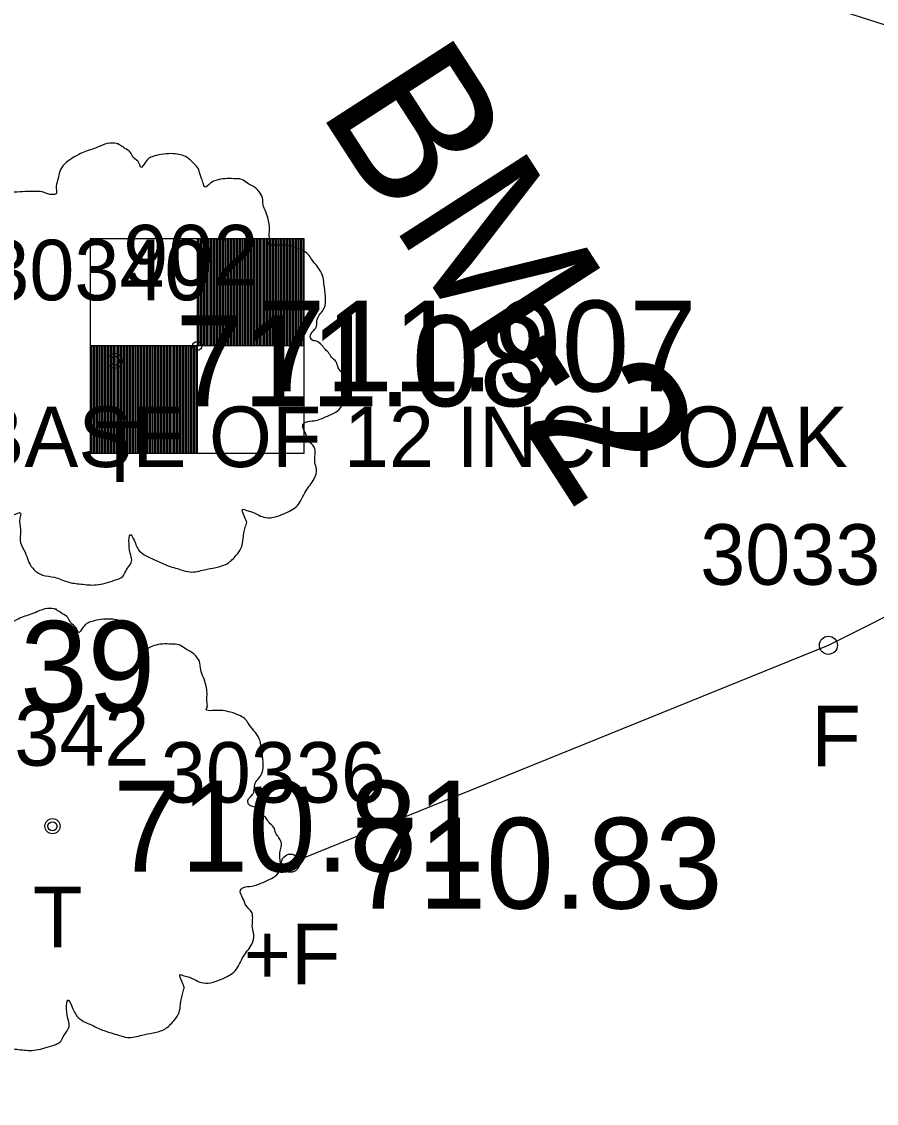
# Model space of a CAD drawing. Extents: x 1375131 to 1378678, y 999028 to 1004053.
# Drawn here: x 1377561.15 to 1377575.26, y 1001420.88 to 1001438.75 of the extents above; entities that cross this region are included whole.
import ezdxf

# ---------------------------------------------------------------- set-up
doc = ezdxf.new("R2010")
doc.units = 0
for name, color, linetype in [('RD_EX_Fence_Other', 7, 'Continuous'), ('RD_EX_Fence_Other_txCode', 7, 'Continuous'), ('RD_EX_SU_Elec', 7, 'Continuous'), ('RD_EX_TX_Fence_Other_ELEV', 7, 'Continuous'), ('RD_EX_TX_VEG_ELEV', 7, 'Continuous'), ('RD_EX_VEG', 7, 'Continuous'), ('RD_EX_VEG_txCode', 7, 'Continuous'), ('RD_HC_Survey', 7, 'Continuous'), ('RD_HC_Survey_ELEV', 7, 'Continuous'), ('RD_HC_Survey_txCode', 7, 'Continuous'), ('RD_SMD_Locator', 7, 'Continuous'), ('RD_TX_Misc1', 7, 'Continuous')]:
    doc.layers.add(name, color=color, linetype=linetype)

msp = doc.modelspace()

# ---------------------------------------------------------------- linework, layer by layer
at = {"layer": 'RD_EX_Fence_Other'}
msp.add_lwpolyline([(1377565.589, 1001424.844), (1377574.472, 1001428.444), (1377584.337, 1001433.395), (1377590.636, 1001436.43)], dxfattribs=at)
at = {"layer": 'RD_EX_SU_Elec'}
msp.add_line((1377525.757, 1001454.692), (1377701.052, 1001398.203), dxfattribs=at)
at = {"layer": 'RD_EX_VEG'}
for centre, radius in [((1377562.69, 1001433.143), 0.125), ((1377562.684, 1001433.134), 0.00005), ((1377561.659, 1001425.455), 0.125), ((1377561.653, 1001425.446), 0.00005)]:
    msp.add_circle(centre, radius, dxfattribs=at)
for points in [[(1377562.756, 1001436.727), (1377562.606, 1001436.739), (1377562.444, 1001436.689), (1377562.319, 1001436.639), (1377562.206, 1001436.602), (1377562.094, 1001436.552), (1377561.944, 1001436.464), (1377561.831, 1001436.364), (1377561.769, 1001436.239), (1377561.744, 1001436.127), (1377561.719, 1001435.989), (1377561.719, 1001435.902), (1377561.656, 1001435.889), (1377561.581, 1001435.902), (1377561.457, 1001435.939), (1377561.332, 1001435.939), (1377561.207, 1001435.939), (1377561.032, 1001435.927), (1377560.857, 1001435.927), (1377560.719, 1001435.902), (1377560.557, 1001435.877), (1377560.37, 1001435.815), (1377560.195, 1001435.752), (1377560.045, 1001435.627), (1377559.92, 1001435.39), (1377559.857, 1001435.215), (1377559.782, 1001435.09), (1377559.857, 1001434.865), (1377559.945, 1001434.69), (1377559.957, 1001434.59), (1377559.995, 1001434.378), (1377560.045, 1001434.265), (1377560.107, 1001434.165), (1377560.07, 1001434.153), (1377559.882, 1001434.128), (1377559.732, 1001434.078), (1377559.52, 1001433.965), (1377559.407, 1001433.853), (1377559.357, 1001433.69), (1377559.345, 1001433.516), (1377559.295, 1001433.416), (1377559.258, 1001433.278), (1377559.245, 1001433.241), (1377559.22, 1001433.078), (1377559.27, 1001432.853), (1377559.283, 1001432.678), (1377559.345, 1001432.566), (1377559.42, 1001432.479), (1377559.507, 1001432.354), (1377559.707, 1001432.241), (1377559.87, 1001432.191), (1377559.97, 1001432.179), (1377559.882, 1001431.929), (1377559.857, 1001431.754), (1377559.795, 1001431.554), (1377559.795, 1001431.516), (1377559.77, 1001431.279), (1377559.845, 1001431.117), (1377559.882, 1001430.929), (1377559.97, 1001430.817), (1377560.107, 1001430.667), (1377560.27, 1001430.554), (1377560.519, 1001430.492), (1377560.719, 1001430.504), (1377561.007, 1001430.592), (1377561.132, 1001430.629), (1377561.119, 1001430.542), (1377561.132, 1001430.354), (1377561.132, 1001430.142), (1377561.207, 1001429.98), (1377561.257, 1001429.842), (1377561.332, 1001429.717), (1377561.494, 1001429.605), (1377561.694, 1001429.567), (1377561.906, 1001429.492), (1377562.131, 1001429.455), (1377562.381, 1001429.442), (1377562.681, 1001429.517), (1377562.818, 1001429.58), (1377562.868, 1001429.667), (1377562.968, 1001429.855), (1377562.943, 1001429.967), (1377562.956, 1001430.267), (1377563.006, 1001430.179), (1377563.093, 1001430.005), (1377563.343, 1001429.855), (1377563.543, 1001429.767), (1377563.781, 1001429.692), (1377563.93, 1001429.655), (1377564.168, 1001429.692), (1377564.355, 1001429.73), (1377564.543, 1001429.792), (1377564.693, 1001429.93), (1377564.78, 1001430.067), (1377564.805, 1001430.204), (1377564.843, 1001430.392), (1377564.868, 1001430.479)], [(1377564.868, 1001430.479), (1377564.83, 1001430.567), (1377564.805, 1001430.692), (1377564.843, 1001430.679), (1377564.93, 1001430.654), (1377565.067, 1001430.592), (1377565.18, 1001430.554), (1377565.342, 1001430.567), (1377565.48, 1001430.617), (1377565.705, 1001430.754), (1377565.842, 1001430.992), (1377565.98, 1001431.192), (1377566.017, 1001431.354), (1377565.992, 1001431.466), (1377565.98, 1001431.716), (1377565.88, 1001431.841), (1377565.855, 1001431.904), (1377565.805, 1001432.104), (1377565.842, 1001432.129), (1377565.98, 1001432.154), (1377566.167, 1001432.216), (1377566.304, 1001432.279), (1377566.417, 1001432.366), (1377566.454, 1001432.479), (1377566.442, 1001432.678), (1377566.467, 1001432.878), (1377566.429, 1001432.953), (1377566.379, 1001433.028), (1377566.342, 1001433.128), (1377566.267, 1001433.203), (1377566.217, 1001433.278), (1377566.167, 1001433.328), (1377566.105, 1001433.403), (1377566.017, 1001433.466), (1377565.942, 1001433.491), (1377565.917, 1001433.566), (1377565.992, 1001433.665), (1377566.017, 1001433.715), (1377566.03, 1001433.828), (1377566.142, 1001434.003), (1377566.167, 1001434.203), (1377566.142, 1001434.415), (1377566.117, 1001434.553), (1377566.042, 1001434.69), (1377565.942, 1001434.815), (1377565.88, 1001434.902), (1377565.792, 1001434.965), (1377565.63, 1001435.027), (1377565.505, 1001435.052), (1377565.33, 1001435.052), (1377565.23, 1001435.077), (1377565.242, 1001435.102), (1377565.242, 1001435.177), (1377565.242, 1001435.315), (1377565.205, 1001435.54), (1377565.13, 1001435.79), (1377565.13, 1001435.802), (1377565.08, 1001435.927), (1377564.968, 1001436.027), (1377564.88, 1001436.077), (1377564.78, 1001436.139), (1377564.655, 1001436.152), (1377564.505, 1001436.152), (1377564.368, 1001436.127), (1377564.268, 1001436.077), (1377564.18, 1001436.014), (1377564.143, 1001436.089), (1377564.093, 1001436.239), (1377564.068, 1001436.314), (1377563.993, 1001436.402), (1377563.881, 1001436.502), (1377563.656, 1001436.564), (1377563.343, 1001436.527), (1377563.193, 1001436.427), (1377563.118, 1001436.339), (1377563.093, 1001436.402), (1377562.993, 1001436.502), (1377562.943, 1001436.589), (1377562.856, 1001436.652), (1377562.781, 1001436.702), (1377562.731, 1001436.727)], [(1377561.725, 1001429.039), (1377561.575, 1001429.051), (1377561.413, 1001429.001), (1377561.288, 1001428.951), (1377561.175, 1001428.914), (1377561.063, 1001428.864), (1377560.913, 1001428.776), (1377560.8, 1001428.676), (1377560.738, 1001428.551), (1377560.713, 1001428.439), (1377560.688, 1001428.301), (1377560.688, 1001428.214), (1377560.625, 1001428.201), (1377560.55, 1001428.214), (1377560.426, 1001428.251), (1377560.301, 1001428.251), (1377560.176, 1001428.251), (1377560.001, 1001428.239), (1377559.826, 1001428.239), (1377559.688, 1001428.214), (1377559.526, 1001428.189), (1377559.339, 1001428.127), (1377559.164, 1001428.064), (1377559.014, 1001427.939), (1377558.889, 1001427.702), (1377558.826, 1001427.527), (1377558.751, 1001427.402), (1377558.826, 1001427.177), (1377558.914, 1001427.002), (1377558.926, 1001426.902), (1377558.964, 1001426.69), (1377559.014, 1001426.577), (1377559.076, 1001426.477), (1377559.039, 1001426.465), (1377558.851, 1001426.44), (1377558.701, 1001426.39), (1377558.489, 1001426.277), (1377558.376, 1001426.165), (1377558.326, 1001426.002), (1377558.314, 1001425.828), (1377558.264, 1001425.728), (1377558.227, 1001425.59), (1377558.214, 1001425.553), (1377558.189, 1001425.39), (1377558.239, 1001425.165), (1377558.252, 1001424.99), (1377558.314, 1001424.878), (1377558.389, 1001424.791), (1377558.476, 1001424.666), (1377558.676, 1001424.553), (1377558.839, 1001424.503), (1377558.939, 1001424.491), (1377558.851, 1001424.241), (1377558.826, 1001424.066), (1377558.764, 1001423.866), (1377558.764, 1001423.828), (1377558.739, 1001423.591), (1377558.814, 1001423.429), (1377558.851, 1001423.241), (1377558.939, 1001423.129), (1377559.076, 1001422.979), (1377559.239, 1001422.866), (1377559.488, 1001422.804), (1377559.688, 1001422.816), (1377559.976, 1001422.904), (1377560.101, 1001422.941), (1377560.088, 1001422.854), (1377560.101, 1001422.666), (1377560.101, 1001422.454), (1377560.176, 1001422.292), (1377560.226, 1001422.154), (1377560.301, 1001422.029), (1377560.463, 1001421.917), (1377560.663, 1001421.879), (1377560.875, 1001421.804), (1377561.1, 1001421.767), (1377561.35, 1001421.754), (1377561.65, 1001421.829), (1377561.787, 1001421.892), (1377561.837, 1001421.979), (1377561.937, 1001422.167), (1377561.912, 1001422.279), (1377561.925, 1001422.579), (1377561.975, 1001422.491), (1377562.062, 1001422.317), (1377562.312, 1001422.167), (1377562.512, 1001422.079), (1377562.75, 1001422.004), (1377562.899, 1001421.967), (1377563.137, 1001422.004), (1377563.324, 1001422.042), (1377563.512, 1001422.104), (1377563.662, 1001422.242), (1377563.749, 1001422.379), (1377563.774, 1001422.516), (1377563.812, 1001422.704), (1377563.837, 1001422.791)], [(1377563.837, 1001422.791), (1377563.799, 1001422.879), (1377563.774, 1001423.004), (1377563.812, 1001422.991), (1377563.899, 1001422.966), (1377564.036, 1001422.904), (1377564.149, 1001422.866), (1377564.311, 1001422.879), (1377564.449, 1001422.929), (1377564.674, 1001423.066), (1377564.811, 1001423.304), (1377564.949, 1001423.504), (1377564.986, 1001423.666), (1377564.961, 1001423.778), (1377564.949, 1001424.028), (1377564.849, 1001424.153), (1377564.824, 1001424.216), (1377564.774, 1001424.416), (1377564.811, 1001424.441), (1377564.949, 1001424.466), (1377565.136, 1001424.528), (1377565.273, 1001424.591), (1377565.386, 1001424.678), (1377565.423, 1001424.791), (1377565.411, 1001424.99), (1377565.436, 1001425.19), (1377565.398, 1001425.265), (1377565.348, 1001425.34), (1377565.311, 1001425.44), (1377565.236, 1001425.515), (1377565.186, 1001425.59), (1377565.136, 1001425.64), (1377565.074, 1001425.715), (1377564.986, 1001425.778), (1377564.911, 1001425.803), (1377564.886, 1001425.878), (1377564.961, 1001425.977), (1377564.986, 1001426.027), (1377564.999, 1001426.14), (1377565.111, 1001426.315), (1377565.136, 1001426.515), (1377565.111, 1001426.727), (1377565.086, 1001426.865), (1377565.011, 1001427.002), (1377564.911, 1001427.127), (1377564.849, 1001427.214), (1377564.761, 1001427.277), (1377564.599, 1001427.339), (1377564.474, 1001427.364), (1377564.299, 1001427.364), (1377564.199, 1001427.389), (1377564.211, 1001427.414), (1377564.211, 1001427.489), (1377564.211, 1001427.627), (1377564.174, 1001427.852), (1377564.099, 1001428.102), (1377564.099, 1001428.114), (1377564.049, 1001428.239), (1377563.937, 1001428.339), (1377563.849, 1001428.389), (1377563.749, 1001428.451), (1377563.624, 1001428.464), (1377563.474, 1001428.464), (1377563.337, 1001428.439), (1377563.237, 1001428.389), (1377563.149, 1001428.326), (1377563.112, 1001428.401), (1377563.062, 1001428.551), (1377563.037, 1001428.626), (1377562.962, 1001428.714), (1377562.85, 1001428.814), (1377562.625, 1001428.876), (1377562.312, 1001428.839), (1377562.162, 1001428.739), (1377562.087, 1001428.651), (1377562.062, 1001428.714), (1377561.962, 1001428.814), (1377561.912, 1001428.901), (1377561.825, 1001428.964), (1377561.75, 1001429.014), (1377561.7, 1001429.039)]]:
    msp.add_spline(points, degree=3, dxfattribs=at)
at = {"layer": 'RD_HC_Survey'}
for p, q in [((1377564.048, 1001435.156), (1377564.048, 1001431.62)), ((1377564.066, 1001435.156), (1377564.066, 1001433.388)), ((1377564.091, 1001435.156), (1377564.091, 1001433.388)), ((1377564.116, 1001435.156), (1377564.116, 1001433.388)), ((1377564.141, 1001435.156), (1377564.141, 1001433.388)), ((1377564.166, 1001435.156), (1377564.166, 1001433.388)), ((1377564.191, 1001435.156), (1377564.191, 1001433.388)), ((1377564.216, 1001435.156), (1377564.216, 1001433.388)), ((1377564.241, 1001435.156), (1377564.241, 1001433.388)), ((1377564.266, 1001435.156), (1377564.266, 1001433.388)), ((1377564.291, 1001435.156), (1377564.291, 1001433.388)), ((1377564.316, 1001435.156), (1377564.316, 1001433.388)), ((1377564.341, 1001435.156), (1377564.341, 1001433.388)), ((1377564.366, 1001435.156), (1377564.366, 1001433.388)), ((1377564.391, 1001435.156), (1377564.391, 1001433.388)), ((1377564.416, 1001435.156), (1377564.416, 1001433.388)), ((1377564.441, 1001435.156), (1377564.441, 1001433.388)), ((1377564.466, 1001435.156), (1377564.466, 1001433.388)), ((1377564.491, 1001435.156), (1377564.491, 1001433.388)), ((1377564.516, 1001435.156), (1377564.516, 1001433.388)), ((1377564.541, 1001435.156), (1377564.541, 1001433.388)), ((1377564.566, 1001435.156), (1377564.566, 1001433.388)), ((1377564.591, 1001435.156), (1377564.591, 1001433.388)), ((1377564.616, 1001435.156), (1377564.616, 1001433.388)), ((1377564.641, 1001435.156), (1377564.641, 1001433.388)), ((1377564.666, 1001435.156), (1377564.666, 1001433.388)), ((1377564.691, 1001435.156), (1377564.691, 1001433.388)), ((1377564.716, 1001435.156), (1377564.716, 1001433.388)), ((1377564.741, 1001435.156), (1377564.741, 1001433.388)), ((1377564.766, 1001435.156), (1377564.766, 1001433.388)), ((1377564.791, 1001435.156), (1377564.791, 1001433.388)), ((1377564.816, 1001435.156), (1377564.816, 1001433.388)), ((1377564.841, 1001435.156), (1377564.841, 1001433.388)), ((1377564.866, 1001435.156), (1377564.866, 1001433.388)), ((1377564.891, 1001435.156), (1377564.891, 1001433.388)), ((1377564.916, 1001435.156), (1377564.916, 1001433.388)), ((1377564.941, 1001435.156), (1377564.941, 1001433.388)), ((1377564.966, 1001435.156), (1377564.966, 1001433.388)), ((1377564.991, 1001435.156), (1377564.991, 1001433.388)), ((1377565.016, 1001435.156), (1377565.016, 1001433.388)), ((1377565.041, 1001435.156), (1377565.041, 1001433.388)), ((1377565.066, 1001435.156), (1377565.066, 1001433.388)), ((1377565.091, 1001435.156), (1377565.091, 1001433.388)), ((1377565.116, 1001435.156), (1377565.116, 1001433.388)), ((1377565.141, 1001435.156), (1377565.141, 1001433.388)), ((1377565.166, 1001435.156), (1377565.166, 1001433.388)), ((1377565.191, 1001435.156), (1377565.191, 1001433.388)), ((1377565.216, 1001435.156), (1377565.216, 1001433.388)), ((1377565.241, 1001435.156), (1377565.241, 1001433.388)), ((1377565.266, 1001435.156), (1377565.266, 1001433.388)), ((1377565.291, 1001435.156), (1377565.291, 1001433.388)), ((1377565.316, 1001435.156), (1377565.316, 1001433.388)), ((1377565.341, 1001435.156), (1377565.341, 1001433.388)), ((1377565.366, 1001435.156), (1377565.366, 1001433.388)), ((1377565.391, 1001435.156), (1377565.391, 1001433.388)), ((1377565.416, 1001435.156), (1377565.416, 1001433.388)), ((1377565.441, 1001435.156), (1377565.441, 1001433.388)), ((1377565.466, 1001435.156), (1377565.466, 1001433.388)), ((1377565.491, 1001435.156), (1377565.491, 1001433.388)), ((1377565.516, 1001435.156), (1377565.516, 1001433.388)), ((1377565.541, 1001435.156), (1377565.541, 1001433.388)), ((1377565.566, 1001435.156), (1377565.566, 1001433.388)), ((1377565.591, 1001435.156), (1377565.591, 1001433.388)), ((1377565.616, 1001435.156), (1377565.616, 1001433.388)), ((1377565.641, 1001435.156), (1377565.641, 1001433.388)), ((1377565.666, 1001435.156), (1377565.666, 1001433.388)), ((1377565.691, 1001435.156), (1377565.691, 1001433.388)), ((1377565.716, 1001435.156), (1377565.716, 1001433.388)), ((1377565.741, 1001435.156), (1377565.741, 1001433.388)), ((1377565.766, 1001435.156), (1377565.766, 1001433.388)), ((1377565.791, 1001435.156), (1377565.791, 1001433.388)), ((1377565.816, 1001433.388), (1377562.28, 1001433.388)), ((1377562.28, 1001433.388), (1377562.28, 1001431.62)), ((1377562.305, 1001433.388), (1377562.305, 1001431.62)), ((1377562.33, 1001433.388), (1377562.33, 1001431.62)), ((1377562.355, 1001433.388), (1377562.355, 1001431.62)), ((1377562.38, 1001433.388), (1377562.38, 1001431.62)), ((1377562.405, 1001433.388), (1377562.405, 1001431.62)), ((1377562.43, 1001433.388), (1377562.43, 1001431.62)), ((1377562.455, 1001433.388), (1377562.455, 1001431.62)), ((1377562.48, 1001433.388), (1377562.48, 1001431.62)), ((1377562.505, 1001433.388), (1377562.505, 1001431.62)), ((1377562.53, 1001433.388), (1377562.53, 1001431.62)), ((1377562.555, 1001433.388), (1377562.555, 1001431.62)), ((1377562.58, 1001433.388), (1377562.58, 1001431.62)), ((1377562.605, 1001433.388), (1377562.605, 1001431.62)), ((1377562.63, 1001433.388), (1377562.63, 1001431.62)), ((1377562.655, 1001433.388), (1377562.655, 1001431.62)), ((1377562.68, 1001433.388), (1377562.68, 1001431.62)), ((1377562.705, 1001433.388), (1377562.705, 1001431.62)), ((1377562.73, 1001433.388), (1377562.73, 1001431.62)), ((1377562.755, 1001433.388), (1377562.755, 1001431.62)), ((1377562.78, 1001433.388), (1377562.78, 1001431.62)), ((1377562.805, 1001433.388), (1377562.805, 1001431.62)), ((1377562.83, 1001433.388), (1377562.83, 1001431.62)), ((1377562.855, 1001433.388), (1377562.855, 1001431.62)), ((1377562.88, 1001433.388), (1377562.88, 1001431.62)), ((1377562.905, 1001433.388), (1377562.905, 1001431.62)), ((1377562.93, 1001433.388), (1377562.93, 1001431.62)), ((1377562.955, 1001433.388), (1377562.955, 1001431.62)), ((1377562.98, 1001433.388), (1377562.98, 1001431.62)), ((1377563.005, 1001433.388), (1377563.005, 1001431.62)), ((1377563.03, 1001433.388), (1377563.03, 1001431.62)), ((1377563.055, 1001433.388), (1377563.055, 1001431.62)), ((1377563.08, 1001433.388), (1377563.08, 1001431.62)), ((1377563.105, 1001433.388), (1377563.105, 1001431.62)), ((1377563.13, 1001433.388), (1377563.13, 1001431.62)), ((1377563.155, 1001433.388), (1377563.155, 1001431.62)), ((1377563.18, 1001433.388), (1377563.18, 1001431.62)), ((1377563.205, 1001433.388), (1377563.205, 1001431.62)), ((1377563.23, 1001433.388), (1377563.23, 1001431.62)), ((1377563.255, 1001433.388), (1377563.255, 1001431.62)), ((1377563.28, 1001433.388), (1377563.28, 1001431.62)), ((1377563.305, 1001433.388), (1377563.305, 1001431.62)), ((1377563.33, 1001433.388), (1377563.33, 1001431.62)), ((1377563.355, 1001433.388), (1377563.355, 1001431.62)), ((1377563.38, 1001433.388), (1377563.38, 1001431.62)), ((1377563.405, 1001433.388), (1377563.405, 1001431.62)), ((1377563.43, 1001433.388), (1377563.43, 1001431.62)), ((1377563.455, 1001433.388), (1377563.455, 1001431.62)), ((1377563.48, 1001433.388), (1377563.48, 1001431.62)), ((1377563.505, 1001433.388), (1377563.505, 1001431.62)), ((1377563.53, 1001433.388), (1377563.53, 1001431.62)), ((1377563.555, 1001433.388), (1377563.555, 1001431.62)), ((1377563.58, 1001433.388), (1377563.58, 1001431.62)), ((1377563.605, 1001433.388), (1377563.605, 1001431.62)), ((1377563.63, 1001433.388), (1377563.63, 1001431.62)), ((1377563.655, 1001433.388), (1377563.655, 1001431.62)), ((1377563.68, 1001433.388), (1377563.68, 1001431.62)), ((1377563.705, 1001433.388), (1377563.705, 1001431.62)), ((1377563.73, 1001433.388), (1377563.73, 1001431.62)), ((1377563.755, 1001433.388), (1377563.755, 1001431.62)), ((1377563.78, 1001433.388), (1377563.78, 1001431.62)), ((1377563.805, 1001433.388), (1377563.805, 1001431.62)), ((1377563.83, 1001433.388), (1377563.83, 1001431.62)), ((1377563.855, 1001433.388), (1377563.855, 1001431.62)), ((1377563.88, 1001433.388), (1377563.88, 1001431.62)), ((1377563.905, 1001433.388), (1377563.905, 1001431.62)), ((1377563.93, 1001433.388), (1377563.93, 1001431.62)), ((1377563.955, 1001433.388), (1377563.955, 1001431.62)), ((1377563.98, 1001433.388), (1377563.98, 1001431.62)), ((1377564.005, 1001433.388), (1377564.005, 1001431.62)), ((1377564.03, 1001433.388), (1377564.03, 1001431.62))]:
    msp.add_line(p, q, dxfattribs=at)
msp.add_lwpolyline([(1377565.816, 1001435.156), (1377562.28, 1001435.156), (1377562.28, 1001431.62), (1377565.816, 1001431.62)], close=True, dxfattribs=at)
at = {"layer": 'RD_SMD_Locator'}
for centre, radius in [((1377564.048, 1001433.388), 0.075), ((1377562.69, 1001433.143), 0.075), ((1377574.472, 1001428.444), 0.15), ((1377561.659, 1001425.455), 0.075), ((1377565.589, 1001424.844), 0.15)]:
    msp.add_circle(centre, radius, dxfattribs=at)

# ---------------------------------------------------------------- texts
at = {"layer": 'RD_EX_Fence_Other_txCode'}
for s, p in [('30337', (1377572.354, 1001429.444)), ('F', (1377574.189, 1001426.444)), ('30336', (1377563.447, 1001425.844)), ('+F', (1377564.817, 1001422.844))]:
    msp.add_text(s, height=1, dxfattribs=at).set_placement(p)
at = {"layer": 'RD_EX_TX_Fence_Other_ELEV'}
msp.add_text('710.83', height=1.5, dxfattribs=at).set_placement((1377566.589, 1001424.094))
at = {"layer": 'RD_EX_TX_VEG_ELEV'}
for s, p in [('711.08', (1377563.69, 1001432.393)), ('710.39', (1377557.221, 1001427.345)), ('710.81', (1377562.659, 1001424.705))]:
    msp.add_text(s, height=1.5, dxfattribs=at).set_placement(p)
at = {"layer": 'RD_EX_VEG_txCode'}
for s, p in [('30340', (1377560.533, 1001434.143)), ('T', (1377562.367, 1001431.143)), ('30342', (1377559.541, 1001426.455)), ('T', (1377561.336, 1001423.455))]:
    msp.add_text(s, height=1, dxfattribs=at).set_placement(p)
at = {"layer": 'RD_HC_Survey_ELEV'}
msp.add_text('711.907', height=1.5, dxfattribs=at).set_placement((1377565.048, 1001432.638))
at = {"layer": 'RD_HC_Survey_txCode'}
for s, p in [('902', (1377562.828, 1001434.388)), ('8 INCH SPIKE IN BASE OF 12 INCH OAK', (1377549.528, 1001431.388))]:
    msp.add_text(s, height=1, dxfattribs=at).set_placement(p)
at = {"layer": 'RD_TX_Misc1'}
msp.add_text('BM-2', height=2.5, rotation=302.8608, dxfattribs=at).set_placement((1377566.03, 1001437.304))

doc.saveas('drawing.dxf')
